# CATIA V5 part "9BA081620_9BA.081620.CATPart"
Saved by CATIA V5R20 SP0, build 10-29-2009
Part number: 9BA081620_9BA.081620
Revision: ANY
Definition: UNKNOWN
Nomenclature: 9BA081620_9BA.081620
Source: Unknown
Bounding box of the stored display mesh (mm): x -10 to 10, y 0 to 25.5, z -10 to 10
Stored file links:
  C:\Users\Utente\Desktop\IO LAVORO\3D X SITO CF\CUMSA\3D files BA\BA 081620\9BA081620_9BA.081620.CATPart
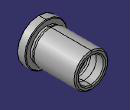
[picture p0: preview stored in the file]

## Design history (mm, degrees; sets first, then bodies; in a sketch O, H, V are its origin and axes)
Body1 "Cortar-Extruir1" (main body)
  Solid1: solid without history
